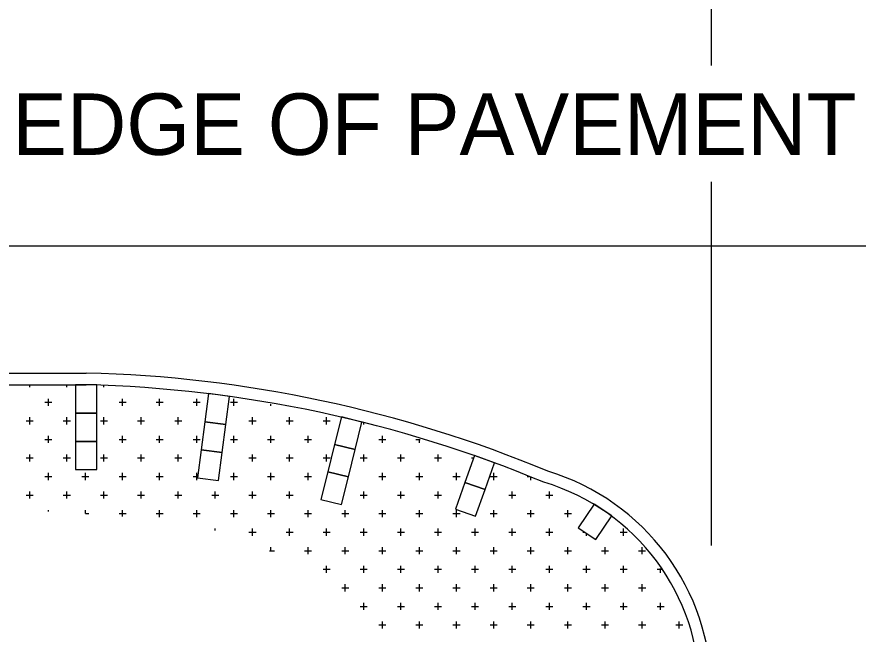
# Model space of a CAD drawing. Extents: x 1312564.5 to 1312581.5, y 1207298.4 to 1207309.4.
# Drawn here: x 1312573.258 to 1312574.353, y 1207306.97 to 1207307.774 of the extents above; entities that cross this region are included whole.
import ezdxf

# ---------------------------------------------------------------- set-up
doc = ezdxf.new("R2010")
doc.units = 0
for name, color, linetype in [('Level 15', 7, 'Continuous'), ('Level 2', 7, 'Continuous'), ('Level 20', 7, 'Continuous'), ('Level 3', 7, 'Continuous'), ('Level 4', 7, 'Continuous')]:
    doc.layers.add(name, color=color, linetype=linetype)

msp = doc.modelspace()

# ---------------------------------------------------------------- linework, layer by layer
at = {"layer": 'Level 15'}
for points in [[(1312574.1624, 1207307.7108), (1312574.1624, 1207308.5818)], [(1312574.1624, 1207307.0855), (1312574.1624, 1207307.559)]]:
    msp.add_lwpolyline(points, dxfattribs=at)
at = {"layer": 'Level 2'}
for p, q in [((1312570.1873, 1207307.31), (1312573.3484, 1207307.31)), ((1312570.1873, 1207307.2948), (1312573.3484, 1207307.2948)), ((1312573.3714, 1207307.2914), (1312573.3714, 1207307.2937)), ((1312573.7097, 1207307.2431), (1312573.7097, 1207307.2455)), ((1312573.8501, 1207307.1994), (1312573.8527, 1207307.1994)), ((1312573.6899, 1207307.1752), (1312573.6902, 1207307.1752)), ((1312573.6568, 1207307.1027), (1312573.666, 1207307.1027)), ((1312573.9951, 1207307.1027), (1312573.9978, 1207307.1027)), ((1312573.9997, 1207307.0981), (1312573.9997, 1207307.1015))]:
    msp.add_line(p, q, dxfattribs=at)
for points in [[(1312573.3622, 1207307.2948), (1312573.3345, 1207307.2948), (1312573.3345, 1207307.2579), (1312573.3622, 1207307.2579)], [(1312573.5349, 1207307.2796), (1312573.5075, 1207307.2832), (1312573.5027, 1207307.2466), (1312573.5301, 1207307.2431)], [(1312573.3622, 1207307.2579), (1312573.3345, 1207307.2579), (1312573.3345, 1207307.221), (1312573.3622, 1207307.221)], [(1312573.7074, 1207307.2461), (1312573.6805, 1207307.2528), (1312573.6717, 1207307.217), (1312573.6985, 1207307.2104)], [(1312573.5301, 1207307.2431), (1312573.5027, 1207307.2466), (1312573.498, 1207307.2101), (1312573.5254, 1207307.2065)], [(1312573.3622, 1207307.221), (1312573.3345, 1207307.221), (1312573.3345, 1207307.1842), (1312573.3622, 1207307.1842)], [(1312573.5254, 1207307.2065), (1312573.498, 1207307.2101), (1312573.4933, 1207307.1735), (1312573.5207, 1207307.17)], [(1312573.6985, 1207307.2104), (1312573.6717, 1207307.217), (1312573.6629, 1207307.1812), (1312573.6897, 1207307.1746)], [(1312573.8798, 1207307.1932), (1312573.8537, 1207307.2024), (1312573.8415, 1207307.1676), (1312573.8676, 1207307.1584)], [(1312573.6897, 1207307.1746), (1312573.6629, 1207307.1812), (1312573.654, 1207307.1454), (1312573.6808, 1207307.1388)], [(1312573.8676, 1207307.1584), (1312573.8415, 1207307.1676), (1312573.8292, 1207307.1328), (1312573.8553, 1207307.1236)], [(1312574.0326, 1207307.1238), (1312574.0096, 1207307.1392), (1312573.9891, 1207307.1085), (1312574.0121, 1207307.0932)]]:
    msp.add_lwpolyline(points, close=True, dxfattribs=at)
for centre, radius, start, end in [((1312573.3077, 1207305.6435), 1.667, 67.3649, 88.6006), ((1312573.3077, 1207305.6435), 1.6517, 67.3374, 88.6006), ((1312573.8629, 1207306.8953), 0.2995, 360, 73.2523), ((1312573.8629, 1207306.8953), 0.2843, 360, 73.4088)]:
    msp.add_arc(centre, radius, start, end, dxfattribs=at)
at = {"layer": 'Level 3'}
msp.add_line((1312570.1873, 1207307.4759), (1312574.4389, 1207307.4759), dxfattribs=at)
at = {"layer": 'Level 4'}
for p, q in [((1312573.2748, 1207307.2914), (1312573.2748, 1207307.2948)), ((1312573.3231, 1207307.2914), (1312573.3231, 1207307.2948)), ((1312573.299, 1207307.2673), (1312573.299, 1207307.2765)), ((1312573.3956, 1207307.2673), (1312573.3956, 1207307.2765)), ((1312573.4439, 1207307.2673), (1312573.4439, 1207307.2765)), ((1312573.4923, 1207307.2673), (1312573.4923, 1207307.2765)), ((1312573.5406, 1207307.2673), (1312573.5406, 1207307.2765)), ((1312573.2943, 1207307.2719), (1312573.3036, 1207307.2719)), ((1312573.391, 1207307.2719), (1312573.4002, 1207307.2719)), ((1312573.4393, 1207307.2719), (1312573.4485, 1207307.2719)), ((1312573.4877, 1207307.2719), (1312573.4969, 1207307.2719)), ((1312573.536, 1207307.2719), (1312573.5452, 1207307.2719)), ((1312573.5889, 1207307.2673), (1312573.5889, 1207307.2696)), ((1312573.2748, 1207307.2431), (1312573.2748, 1207307.2523)), ((1312573.3231, 1207307.2431), (1312573.3231, 1207307.2523)), ((1312573.3714, 1207307.2431), (1312573.3714, 1207307.2523)), ((1312573.4198, 1207307.2431), (1312573.4198, 1207307.2523)), ((1312573.4681, 1207307.2431), (1312573.4681, 1207307.2523)), ((1312573.5648, 1207307.2431), (1312573.5648, 1207307.2523)), ((1312573.6131, 1207307.2431), (1312573.6131, 1207307.2523)), ((1312573.6614, 1207307.2431), (1312573.6614, 1207307.2523)), ((1312573.2702, 1207307.2477), (1312573.2794, 1207307.2477)), ((1312573.3185, 1207307.2477), (1312573.3277, 1207307.2477)), ((1312573.3668, 1207307.2477), (1312573.376, 1207307.2477)), ((1312573.4152, 1207307.2477), (1312573.4244, 1207307.2477)), ((1312573.4635, 1207307.2477), (1312573.4727, 1207307.2477)), ((1312573.5601, 1207307.2477), (1312573.5694, 1207307.2477)), ((1312573.6085, 1207307.2477), (1312573.6177, 1207307.2477)), ((1312573.6568, 1207307.2477), (1312573.666, 1207307.2477)), ((1312573.2943, 1207307.2235), (1312573.3036, 1207307.2235)), ((1312573.299, 1207307.2189), (1312573.299, 1207307.2282)), ((1312573.391, 1207307.2235), (1312573.4002, 1207307.2235)), ((1312573.3956, 1207307.2189), (1312573.3956, 1207307.2282)), ((1312573.4393, 1207307.2235), (1312573.4485, 1207307.2235)), ((1312573.4439, 1207307.2189), (1312573.4439, 1207307.2282)), ((1312573.4877, 1207307.2235), (1312573.4969, 1207307.2235)), ((1312573.4923, 1207307.2189), (1312573.4923, 1207307.2282)), ((1312573.536, 1207307.2235), (1312573.5452, 1207307.2235)), ((1312573.5406, 1207307.2189), (1312573.5406, 1207307.2282)), ((1312573.5843, 1207307.2235), (1312573.5935, 1207307.2235)), ((1312573.5889, 1207307.2189), (1312573.5889, 1207307.2282)), ((1312573.6326, 1207307.2235), (1312573.6372, 1207307.2235)), ((1312573.6372, 1207307.2189), (1312573.6372, 1207307.2282)), ((1312573.6372, 1207307.2235), (1312573.6418, 1207307.2235)), ((1312573.7293, 1207307.2235), (1312573.7385, 1207307.2235)), ((1312573.7339, 1207307.2189), (1312573.7339, 1207307.2282)), ((1312573.7776, 1207307.2235), (1312573.783, 1207307.2235)), ((1312573.7822, 1207307.2189), (1312573.7822, 1207307.2238)), ((1312573.2702, 1207307.1994), (1312573.2794, 1207307.1994)), ((1312573.2748, 1207307.1948), (1312573.2748, 1207307.204)), ((1312573.3185, 1207307.1994), (1312573.3277, 1207307.1994)), ((1312573.3231, 1207307.1948), (1312573.3231, 1207307.204)), ((1312573.3668, 1207307.1994), (1312573.376, 1207307.1994)), ((1312573.3714, 1207307.1948), (1312573.3714, 1207307.204)), ((1312573.4152, 1207307.1994), (1312573.4244, 1207307.1994)), ((1312573.4198, 1207307.1948), (1312573.4198, 1207307.204)), ((1312573.4635, 1207307.1994), (1312573.4727, 1207307.1994)), ((1312573.4681, 1207307.1948), (1312573.4681, 1207307.204)), ((1312573.5601, 1207307.1994), (1312573.5694, 1207307.1994)), ((1312573.5648, 1207307.1948), (1312573.5648, 1207307.204)), ((1312573.6085, 1207307.1994), (1312573.6177, 1207307.1994)), ((1312573.6131, 1207307.1948), (1312573.6131, 1207307.204)), ((1312573.6568, 1207307.1994), (1312573.666, 1207307.1994)), ((1312573.6614, 1207307.1948), (1312573.6614, 1207307.204)), ((1312573.7051, 1207307.1994), (1312573.7143, 1207307.1994)), ((1312573.7097, 1207307.1948), (1312573.7097, 1207307.204)), ((1312573.7535, 1207307.1994), (1312573.7627, 1207307.1994)), ((1312573.7581, 1207307.1948), (1312573.7581, 1207307.204)), ((1312573.8018, 1207307.1994), (1312573.811, 1207307.1994)), ((1312573.8064, 1207307.1948), (1312573.8064, 1207307.204)), ((1312573.299, 1207307.1706), (1312573.299, 1207307.1798)), ((1312573.3473, 1207307.1706), (1312573.3473, 1207307.1798)), ((1312573.3956, 1207307.1706), (1312573.3956, 1207307.1798)), ((1312573.4439, 1207307.1706), (1312573.4439, 1207307.1798)), ((1312573.4923, 1207307.1706), (1312573.4923, 1207307.1798)), ((1312573.5406, 1207307.1706), (1312573.5406, 1207307.1798)), ((1312573.5889, 1207307.1706), (1312573.5889, 1207307.1798)), ((1312573.6372, 1207307.1706), (1312573.6372, 1207307.1798)), ((1312573.7339, 1207307.1706), (1312573.7339, 1207307.1798)), ((1312573.7822, 1207307.1706), (1312573.7822, 1207307.1798)), ((1312573.8306, 1207307.1706), (1312573.8306, 1207307.1798)), ((1312573.8789, 1207307.1706), (1312573.8789, 1207307.1798)), ((1312573.2943, 1207307.1752), (1312573.3036, 1207307.1752)), ((1312573.3427, 1207307.1752), (1312573.3473, 1207307.1752)), ((1312573.3473, 1207307.1752), (1312573.3519, 1207307.1752)), ((1312573.391, 1207307.1752), (1312573.4002, 1207307.1752)), ((1312573.4393, 1207307.1752), (1312573.4485, 1207307.1752)), ((1312573.4877, 1207307.1752), (1312573.4935, 1207307.1752)), ((1312573.536, 1207307.1752), (1312573.5452, 1207307.1752)), ((1312573.5843, 1207307.1752), (1312573.5935, 1207307.1752)), ((1312573.6326, 1207307.1752), (1312573.6372, 1207307.1752)), ((1312573.6372, 1207307.1752), (1312573.6418, 1207307.1752)), ((1312573.7293, 1207307.1752), (1312573.7385, 1207307.1752)), ((1312573.7776, 1207307.1752), (1312573.7868, 1207307.1752)), ((1312573.8259, 1207307.1752), (1312573.8352, 1207307.1752)), ((1312573.8743, 1207307.1752), (1312573.8835, 1207307.1752)), ((1312573.9226, 1207307.1752), (1312573.9251, 1207307.1752)), ((1312573.9272, 1207307.1706), (1312573.9272, 1207307.1744)), ((1312573.2748, 1207307.1464), (1312573.2748, 1207307.1557)), ((1312573.3231, 1207307.1464), (1312573.3231, 1207307.1557)), ((1312573.3714, 1207307.1464), (1312573.3714, 1207307.1557)), ((1312573.4198, 1207307.1464), (1312573.4198, 1207307.1557)), ((1312573.4681, 1207307.1464), (1312573.4681, 1207307.1557)), ((1312573.5164, 1207307.1464), (1312573.5164, 1207307.1557)), ((1312573.5648, 1207307.1464), (1312573.5648, 1207307.1557)), ((1312573.6131, 1207307.1464), (1312573.6131, 1207307.1557)), ((1312573.7097, 1207307.1464), (1312573.7097, 1207307.1557)), ((1312573.7581, 1207307.1464), (1312573.7581, 1207307.1557)), ((1312573.8064, 1207307.1464), (1312573.8064, 1207307.1557)), ((1312573.903, 1207307.1464), (1312573.903, 1207307.1557)), ((1312573.9514, 1207307.1464), (1312573.9514, 1207307.1557)), ((1312573.2702, 1207307.1511), (1312573.2794, 1207307.1511)), ((1312573.3185, 1207307.1511), (1312573.3277, 1207307.1511)), ((1312573.3668, 1207307.1511), (1312573.376, 1207307.1511)), ((1312573.4152, 1207307.1511), (1312573.4244, 1207307.1511)), ((1312573.4635, 1207307.1511), (1312573.4727, 1207307.1511)), ((1312573.5118, 1207307.1511), (1312573.521, 1207307.1511)), ((1312573.5601, 1207307.1511), (1312573.5694, 1207307.1511)), ((1312573.6085, 1207307.1511), (1312573.6177, 1207307.1511)), ((1312573.7051, 1207307.1511), (1312573.7143, 1207307.1511)), ((1312573.7535, 1207307.1511), (1312573.7627, 1207307.1511)), ((1312573.8018, 1207307.1511), (1312573.811, 1207307.1511)), ((1312573.8984, 1207307.1511), (1312573.9076, 1207307.1511)), ((1312573.9468, 1207307.1511), (1312573.956, 1207307.1511)), ((1312573.299, 1207307.1298), (1312573.299, 1207307.1315)), ((1312573.3473, 1207307.1269), (1312573.3473, 1207307.1315)), ((1312573.3956, 1207307.1269), (1312573.3956, 1207307.1315)), ((1312573.4439, 1207307.1269), (1312573.4439, 1207307.1315)), ((1312573.4923, 1207307.1269), (1312573.4923, 1207307.1315)), ((1312573.5406, 1207307.1269), (1312573.5406, 1207307.1315)), ((1312573.5889, 1207307.1269), (1312573.5889, 1207307.1315)), ((1312573.6372, 1207307.1269), (1312573.6372, 1207307.1315)), ((1312573.6856, 1207307.1269), (1312573.6856, 1207307.1315)), ((1312573.7339, 1207307.1269), (1312573.7339, 1207307.1315)), ((1312573.7822, 1207307.1269), (1312573.7822, 1207307.1315)), ((1312573.8306, 1207307.1269), (1312573.8306, 1207307.1315)), ((1312573.8789, 1207307.1269), (1312573.8789, 1207307.1315)), ((1312573.9272, 1207307.1269), (1312573.9272, 1207307.1315)), ((1312573.9755, 1207307.1269), (1312573.9755, 1207307.1315)), ((1312573.3473, 1207307.1269), (1312573.3519, 1207307.1269)), ((1312573.391, 1207307.1269), (1312573.4002, 1207307.1269)), ((1312573.3956, 1207307.1231), (1312573.3956, 1207307.1269)), ((1312573.4393, 1207307.1269), (1312573.4485, 1207307.1269)), ((1312573.4439, 1207307.1223), (1312573.4439, 1207307.1269)), ((1312573.4877, 1207307.1269), (1312573.4969, 1207307.1269)), ((1312573.4923, 1207307.1223), (1312573.4923, 1207307.1269)), ((1312573.536, 1207307.1269), (1312573.5452, 1207307.1269)), ((1312573.5406, 1207307.1223), (1312573.5406, 1207307.1269)), ((1312573.5843, 1207307.1269), (1312573.5935, 1207307.1269)), ((1312573.5889, 1207307.1223), (1312573.5889, 1207307.1269)), ((1312573.6326, 1207307.1269), (1312573.6372, 1207307.1269)), ((1312573.6372, 1207307.1223), (1312573.6372, 1207307.1269)), ((1312573.6372, 1207307.1269), (1312573.6418, 1207307.1269)), ((1312573.681, 1207307.1269), (1312573.6902, 1207307.1269)), ((1312573.6856, 1207307.1223), (1312573.6856, 1207307.1269)), ((1312573.7293, 1207307.1269), (1312573.7385, 1207307.1269)), ((1312573.7339, 1207307.1223), (1312573.7339, 1207307.1269)), ((1312573.7776, 1207307.1269), (1312573.7868, 1207307.1269)), ((1312573.7822, 1207307.1223), (1312573.7822, 1207307.1269)), ((1312573.8259, 1207307.1269), (1312573.8352, 1207307.1269)), ((1312573.8306, 1207307.1223), (1312573.8306, 1207307.1269)), ((1312573.8743, 1207307.1269), (1312573.8835, 1207307.1269)), ((1312573.8789, 1207307.1223), (1312573.8789, 1207307.1269)), ((1312573.9226, 1207307.1269), (1312573.9272, 1207307.1269)), ((1312573.9272, 1207307.1223), (1312573.9272, 1207307.1269)), ((1312573.9272, 1207307.1269), (1312573.9318, 1207307.1269)), ((1312573.9709, 1207307.1269), (1312573.9801, 1207307.1269)), ((1312573.9755, 1207307.1223), (1312573.9755, 1207307.1269)), ((1312573.5164, 1207307.1049), (1312573.5164, 1207307.1073)), ((1312573.5601, 1207307.1027), (1312573.5694, 1207307.1027)), ((1312573.5648, 1207307.0981), (1312573.5648, 1207307.1073)), ((1312573.6085, 1207307.1027), (1312573.6177, 1207307.1027)), ((1312573.6131, 1207307.0981), (1312573.6131, 1207307.1073)), ((1312573.6614, 1207307.0981), (1312573.6614, 1207307.1073)), ((1312573.7051, 1207307.1027), (1312573.7143, 1207307.1027)), ((1312573.7097, 1207307.0981), (1312573.7097, 1207307.1073)), ((1312573.7535, 1207307.1027), (1312573.7627, 1207307.1027)), ((1312573.7581, 1207307.0981), (1312573.7581, 1207307.1073)), ((1312573.8018, 1207307.1027), (1312573.811, 1207307.1027)), ((1312573.8064, 1207307.0981), (1312573.8064, 1207307.1073)), ((1312573.8501, 1207307.1027), (1312573.8593, 1207307.1027)), ((1312573.8547, 1207307.0981), (1312573.8547, 1207307.1073)), ((1312573.8984, 1207307.1027), (1312573.9076, 1207307.1027)), ((1312573.903, 1207307.0981), (1312573.903, 1207307.1073)), ((1312573.9468, 1207307.1027), (1312573.956, 1207307.1027)), ((1312573.9514, 1207307.0981), (1312573.9514, 1207307.1073)), ((1312574.0434, 1207307.1027), (1312574.0526, 1207307.1027)), ((1312574.048, 1207307.0981), (1312574.048, 1207307.1073)), ((1312573.5869, 1207307.0786), (1312573.5935, 1207307.0786)), ((1312573.5889, 1207307.0775), (1312573.5889, 1207307.0832)), ((1312573.6326, 1207307.0786), (1312573.6372, 1207307.0786)), ((1312573.6372, 1207307.074), (1312573.6372, 1207307.0832)), ((1312573.6372, 1207307.0786), (1312573.6418, 1207307.0786)), ((1312573.681, 1207307.0786), (1312573.6902, 1207307.0786)), ((1312573.6856, 1207307.074), (1312573.6856, 1207307.0832)), ((1312573.7293, 1207307.0786), (1312573.7385, 1207307.0786)), ((1312573.7339, 1207307.074), (1312573.7339, 1207307.0832)), ((1312573.7776, 1207307.0786), (1312573.7868, 1207307.0786)), ((1312573.7822, 1207307.074), (1312573.7822, 1207307.0832)), ((1312573.8259, 1207307.0786), (1312573.8352, 1207307.0786)), ((1312573.8306, 1207307.074), (1312573.8306, 1207307.0832)), ((1312573.8743, 1207307.0786), (1312573.8835, 1207307.0786)), ((1312573.8789, 1207307.074), (1312573.8789, 1207307.0832)), ((1312573.9226, 1207307.0786), (1312573.9272, 1207307.0786)), ((1312573.9272, 1207307.074), (1312573.9272, 1207307.0832)), ((1312573.9272, 1207307.0786), (1312573.9318, 1207307.0786)), ((1312573.9709, 1207307.0786), (1312573.9801, 1207307.0786)), ((1312573.9755, 1207307.074), (1312573.9755, 1207307.0832)), ((1312574.0192, 1207307.0786), (1312574.0285, 1207307.0786)), ((1312574.0239, 1207307.074), (1312574.0239, 1207307.0832)), ((1312574.0676, 1207307.0786), (1312574.0764, 1207307.0786)), ((1312574.0722, 1207307.074), (1312574.0722, 1207307.0832)), ((1312573.6614, 1207307.0498), (1312573.6614, 1207307.059)), ((1312573.7097, 1207307.0498), (1312573.7097, 1207307.059)), ((1312573.7581, 1207307.0498), (1312573.7581, 1207307.059)), ((1312573.8064, 1207307.0498), (1312573.8064, 1207307.059)), ((1312573.8547, 1207307.0498), (1312573.8547, 1207307.059)), ((1312573.903, 1207307.0498), (1312573.903, 1207307.059)), ((1312573.9514, 1207307.0498), (1312573.9514, 1207307.059)), ((1312573.9997, 1207307.0498), (1312573.9997, 1207307.059)), ((1312574.048, 1207307.0498), (1312574.048, 1207307.059)), ((1312574.0963, 1207307.0498), (1312574.0963, 1207307.0556)), ((1312573.6568, 1207307.0544), (1312573.666, 1207307.0544)), ((1312573.7051, 1207307.0544), (1312573.7143, 1207307.0544)), ((1312573.7535, 1207307.0544), (1312573.7627, 1207307.0544)), ((1312573.8018, 1207307.0544), (1312573.811, 1207307.0544)), ((1312573.8501, 1207307.0544), (1312573.8593, 1207307.0544)), ((1312573.8984, 1207307.0544), (1312573.9076, 1207307.0544)), ((1312573.9468, 1207307.0544), (1312573.956, 1207307.0544)), ((1312573.9951, 1207307.0544), (1312574.0043, 1207307.0544)), ((1312574.0434, 1207307.0544), (1312574.0526, 1207307.0544)), ((1312574.0917, 1207307.0544), (1312574.0974, 1207307.0544)), ((1312573.6856, 1207307.0256), (1312573.6856, 1207307.0348)), ((1312573.7339, 1207307.0256), (1312573.7339, 1207307.0348)), ((1312573.7822, 1207307.0256), (1312573.7822, 1207307.0348)), ((1312573.8306, 1207307.0256), (1312573.8306, 1207307.0348)), ((1312573.8789, 1207307.0256), (1312573.8789, 1207307.0348)), ((1312573.9272, 1207307.0256), (1312573.9272, 1207307.0348)), ((1312573.9755, 1207307.0256), (1312573.9755, 1207307.0348)), ((1312574.0239, 1207307.0256), (1312574.0239, 1207307.0348)), ((1312574.0722, 1207307.0256), (1312574.0722, 1207307.0348)), ((1312573.681, 1207307.0302), (1312573.6902, 1207307.0302)), ((1312573.7293, 1207307.0302), (1312573.7385, 1207307.0302)), ((1312573.7776, 1207307.0302), (1312573.7868, 1207307.0302)), ((1312573.8259, 1207307.0302), (1312573.8352, 1207307.0302)), ((1312573.8743, 1207307.0302), (1312573.8835, 1207307.0302)), ((1312573.9226, 1207307.0302), (1312573.9272, 1207307.0302)), ((1312573.9272, 1207307.0302), (1312573.9318, 1207307.0302)), ((1312573.9709, 1207307.0302), (1312573.9801, 1207307.0302)), ((1312574.0192, 1207307.0302), (1312574.0285, 1207307.0302)), ((1312574.0676, 1207307.0302), (1312574.0768, 1207307.0302)), ((1312573.7051, 1207307.0061), (1312573.7143, 1207307.0061)), ((1312573.7097, 1207307.0015), (1312573.7097, 1207307.0107)), ((1312573.7535, 1207307.0061), (1312573.7627, 1207307.0061)), ((1312573.7581, 1207307.0015), (1312573.7581, 1207307.0107)), ((1312573.8018, 1207307.0061), (1312573.811, 1207307.0061)), ((1312573.8064, 1207307.0015), (1312573.8064, 1207307.0107)), ((1312573.8501, 1207307.0061), (1312573.8593, 1207307.0061)), ((1312573.8547, 1207307.0015), (1312573.8547, 1207307.0107)), ((1312573.8984, 1207307.0061), (1312573.9076, 1207307.0061)), ((1312573.903, 1207307.0015), (1312573.903, 1207307.0107)), ((1312573.9468, 1207307.0061), (1312573.956, 1207307.0061)), ((1312573.9514, 1207307.0015), (1312573.9514, 1207307.0107)), ((1312573.9951, 1207307.0061), (1312574.0043, 1207307.0061)), ((1312573.9997, 1207307.0015), (1312573.9997, 1207307.0107)), ((1312574.0434, 1207307.0061), (1312574.0526, 1207307.0061)), ((1312574.048, 1207307.0015), (1312574.048, 1207307.0107)), ((1312574.0917, 1207307.0061), (1312574.101, 1207307.0061)), ((1312574.0963, 1207307.0015), (1312574.0963, 1207307.0107)), ((1312573.7293, 1207306.9819), (1312573.7385, 1207306.9819)), ((1312573.7339, 1207306.9773), (1312573.7339, 1207306.9865)), ((1312573.7776, 1207306.9819), (1312573.7868, 1207306.9819)), ((1312573.7822, 1207306.9773), (1312573.7822, 1207306.9865)), ((1312573.8259, 1207306.9819), (1312573.8352, 1207306.9819)), ((1312573.8306, 1207306.9773), (1312573.8306, 1207306.9865)), ((1312573.8743, 1207306.9819), (1312573.8835, 1207306.9819)), ((1312573.8789, 1207306.9773), (1312573.8789, 1207306.9865)), ((1312573.9226, 1207306.9819), (1312573.9272, 1207306.9819)), ((1312573.9272, 1207306.9773), (1312573.9272, 1207306.9865)), ((1312573.9272, 1207306.9819), (1312573.9318, 1207306.9819)), ((1312573.9709, 1207306.9819), (1312573.9801, 1207306.9819)), ((1312573.9755, 1207306.9773), (1312573.9755, 1207306.9865)), ((1312574.0192, 1207306.9819), (1312574.0285, 1207306.9819)), ((1312574.0239, 1207306.9773), (1312574.0239, 1207306.9865)), ((1312574.0676, 1207306.9819), (1312574.0768, 1207306.9819)), ((1312574.0722, 1207306.9773), (1312574.0722, 1207306.9865)), ((1312574.1159, 1207306.9819), (1312574.1251, 1207306.9819)), ((1312574.1205, 1207306.9773), (1312574.1205, 1207306.9865))]:
    msp.add_line(p, q, dxfattribs=at)

# ---------------------------------------------------------------- texts
at = {"layer": 'Level 20'}
msp.add_text('EDGE OF PAVEMENT', height=0.08, dxfattribs=at).set_placement((1312573.2519, 1207307.5942))

doc.saveas('drawing.dxf')
